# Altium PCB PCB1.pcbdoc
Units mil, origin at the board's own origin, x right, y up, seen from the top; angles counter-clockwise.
Board outline 7296.38 x 4966.72 mil, 2 copper layers (Top Layer, Bottom Layer), stack 62.206 mil thick; 66 components, 34 nets, 136 pads, 49 vias.
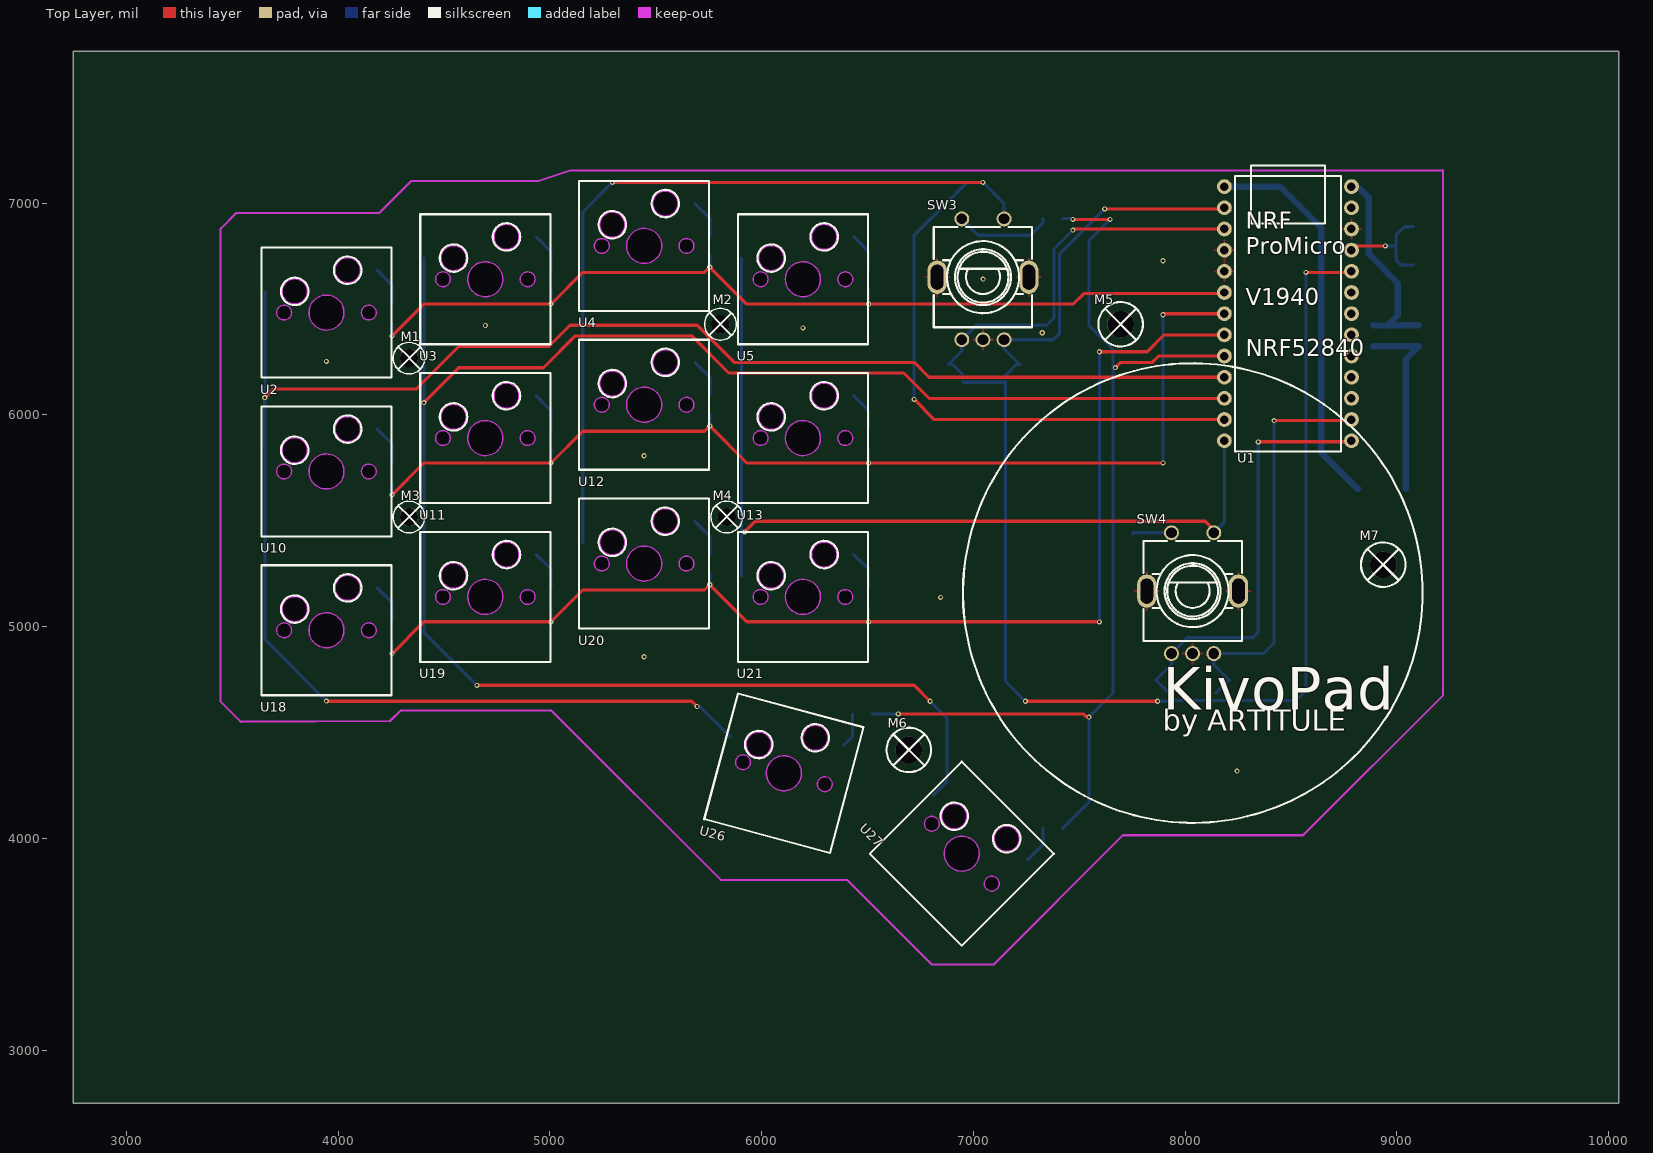
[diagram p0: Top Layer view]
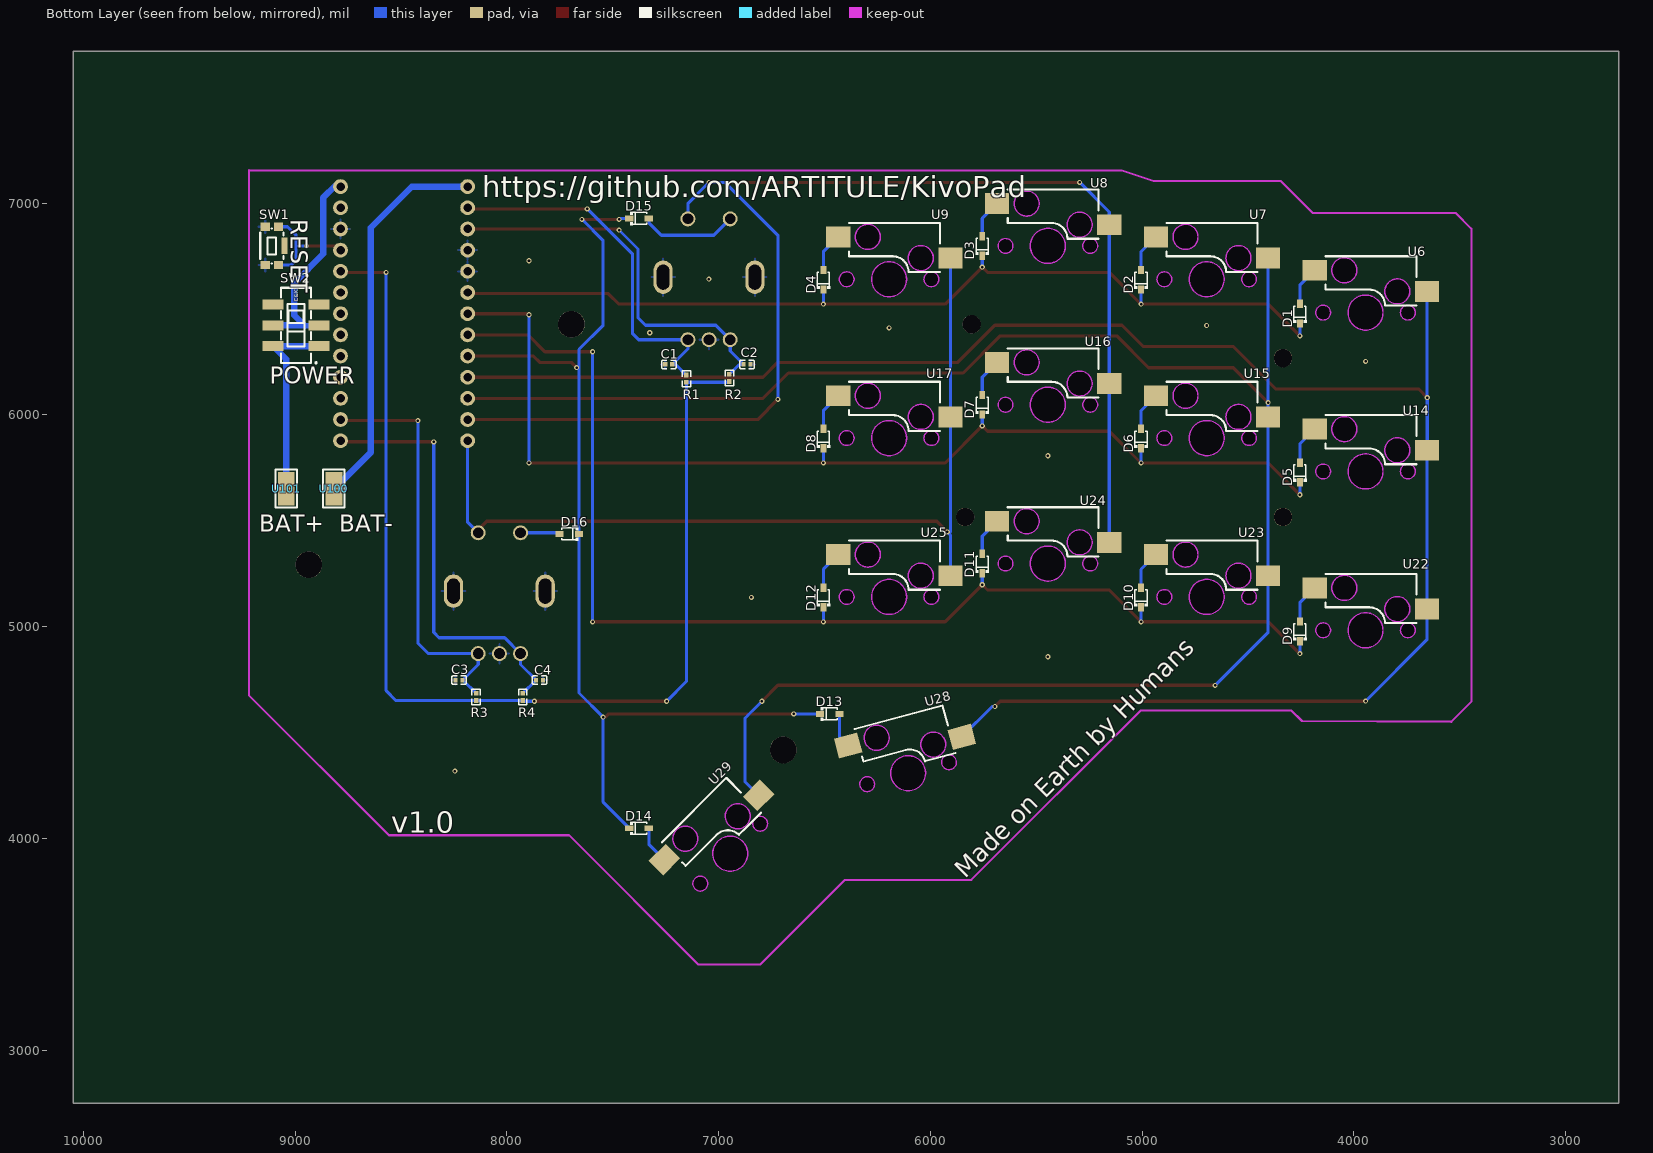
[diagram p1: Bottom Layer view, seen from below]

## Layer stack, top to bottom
Top Solder Mask Layer: solder mask 0.394, Dk 3.3
Top Layer: signal copper 1.379
Dielectric1: surface 59.449, FR4, Dk 4.5
Bottom Layer: signal copper 1.378
Bottom Solder Mask Layer: solder mask 0.394, Dk 3.3

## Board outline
10046.38,2750 2750,2750 2750,7716.72 10046.38,7716.72

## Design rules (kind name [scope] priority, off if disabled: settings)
BoardOutlineClearance copperThickness1oz [All] p0: genericclearance=10 ignorepadtopadclearanceinfootprint=FALSE except(0: Arc-SplitContinuation Track-SplitContinuation SMDPad-SplitContinuation THPad-SplitContinuation Via-SplitContinuation Fill-SplitContinuation Poly-SplitContinuation Region-SplitContinuation Text-SplitContinuation)
BoardOutlineClearance copperThickness2oz [All] p0: genericclearance=10 ignorepadtopadclearanceinfootprint=FALSE except(0: Arc-SplitContinuation Track-SplitContinuation SMDPad-SplitContinuation THPad-SplitContinuation Via-SplitContinuation Fill-SplitContinuation Poly-SplitContinuation Region-SplitContinuation Text-SplitContinuation)
BoardOutlineClearance otherClearance [All] p0: genericclearance=10 ignorepadtopadclearanceinfootprint=FALSE except(0: Arc-SplitContinuation Track-SplitContinuation SMDPad-SplitContinuation THPad-SplitContinuation Via-SplitContinuation Fill-SplitContinuation Poly-SplitContinuation Region-SplitContinuation Text-SplitContinuation)
Clearance copperThickness1oz [All] p1: gap=7 ignorepadtopadclearanceinfootprint=FALSE
Clearance copperThickness2oz [All] p1: gap=7 ignorepadtopadclearanceinfootprint=FALSE
Clearance otherClearance [All] p1: gap=7 ignorepadtopadclearanceinfootprint=FALSE
DiffPairsRouting differentialPair [All] p1: maxuncoupledlength=10 minlimit=6 maxlimit=Infinity mostfreqgap=6 toplayer_minwidth=5 toplayer_prefwidth=10 toplayer_maxwidth=100 bottomlayer_minwidth=5 bottomlayer_prefwidth=10 bottomlayer_maxwidth=100
PasteMaskExpansion pasteMaskExpansion [All] p1: expansion=0
PlaneConnect innerPlane [All] p1: planeconnectstyle=Relief reliefexpansion=20 reliefentries=4 reliefconductorwidth=10 reliefairgap=10
PolygonConnect copperRegion [All] p1: connectstyle=Relief reliefentries=4 reliefconductorwidth=10 polygonreliefangle="90 Angle" airgapwidth=10
RoutingVias viaSize [All] p1: viastyle="Through Hole" holewidth=12.0078 minholewidth=11.811 maxholewidth=248.0314 width=12.0078 minwidth=11.811 maxwidth=248.0314
SolderMaskExpansion solderMaskExpansion [IsVia] p1: useseparateexpansions=TRUE expansion=-1000 expansionbottom=-1000
SolderMaskExpansion solderMaskExpansion [All] p2: useseparateexpansions=TRUE expansion=2 expansionbottom=2
Width copperThickness1oz [All] p1: maxlimit=100 minlimit=5 preferedwidth=10
Width copperThickness2oz [All] p1: maxlimit=100 minlimit=8 preferedwidth=10

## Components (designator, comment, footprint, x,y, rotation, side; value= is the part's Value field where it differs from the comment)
C1 "100nF" C0402 7234.99,6238.32 r180 bottom
C2 "100nF" C0402 6864.99,6238.32 r0 bottom
C3 "100nF" C0402 8224.99,4748.32 r180 bottom
C4 "100nF" C0402 7844.99,4748.32 r0 bottom
D1 "1N4148WS" SOD-323_L1.8-W1.3-LS2.5-RD 4254.99,6478.32 r90 bottom
D2 "1N4148WS" SOD-323_L1.8-W1.3-LS2.5-RD 5004.99,6638.32 r90 bottom
D3 "1N4148WS" SOD-323_L1.8-W1.3-LS2.5-RD 5754.99,6798.32 r90 bottom
D4 "1N4148WS" SOD-323_L1.8-W1.3-LS2.5-RD 6504.99,6638.32 r90 bottom
D5 "1N4148WS" SOD-323_L1.8-W1.3-LS2.5-RD 4254.99,5728.32 r90 bottom
D6 "1N4148WS" SOD-323_L1.8-W1.3-LS2.5-RD 5004.99,5888.32 r90 bottom
D7 "1N4148WS" SOD-323_L1.8-W1.3-LS2.5-RD 5754.99,6048.32 r90 bottom
D8 "1N4148WS" SOD-323_L1.8-W1.3-LS2.5-RD 6504.99,5888.32 r90 bottom
D9 "1N4148WS" SOD-323_L1.8-W1.3-LS2.5-RD 4254.99,4978.32 r90 bottom
D10 "1N4148WS" SOD-323_L1.8-W1.3-LS2.5-RD 5004.99,5138.32 r90 bottom
D11 "1N4148WS" SOD-323_L1.8-W1.3-LS2.5-RD 5754.99,5298.32 r90 bottom
D12 "1N4148WS" SOD-323_L1.8-W1.3-LS2.5-RD 6504.99,5138.32 r90 bottom
D13 "1N4148WS" SOD-323_L1.8-W1.3-LS2.5-RD 6474.99,4588.32 r180 bottom
D14 "1N4148WS" SOD-323_L1.8-W1.3-LS2.5-RD 7374.99,4048.32 r180 bottom
D15 "1N4148WS" SOD-323_L1.8-W1.3-LS2.5-RD 7374.99,6928.32 r180 bottom
D16 "1N4148WS" SOD-323_L1.8-W1.3-LS2.5-RD 7704.99,5438.32 r0 bottom
M1 "" Screw-Hole-M2 4334.99,6268.32 r0 top
M2 "" Screw-Hole-M2 5804.99,6428.32 r0 top
M3 "" Screw-Hole-M2 4334.99,5518.32 r0 top
M4 "" Screw-Hole-M2 5834.99,5518.32 r0 top
M5 "" Screw-Hole-M3 7694.99,6428.32 r0 top
M6 "" Screw-Hole-M3 6694.99,4418.32 r0 top
M7 "" Screw-Hole-M3 8934.9,5293.05 r0 top
R1 "5.1kΩ" R0402 7152.03,6171.28 r90 bottom
R2 "5.1kΩ" R0402 6948.42,6174.63 r90 bottom
R3 "5.1kΩ" R0402 8144.99,4668.32 r90 bottom
R4 "5.1kΩ" R0402 7924.99,4668.32 r90 bottom
SW1 "KMR221GLFS" KEY-SMD_KMR2XXGXXX 9094.99,6798.32 r270 bottom
SW2 "JS202011SCQN" SW-SMD_JS202011SCQN 8994.99,6423.32 r90 bottom
SW3 "EC11E15244B2" SW-TH_EC11XXXXXXXX 7045.03,6640.79 r0 top
SW4 "EC11E15244B2" SW-TH_EC11XXXXXXXX 8034.99,5158.32 r0 top
U1 "NRF_ProMicro" NRF_Pro_Micro 8484.99,6478.32 r0 top
U2 "CPG151101D13" KEY-TH_CPG151101D21X#1 3944.99,6483.36 r0 top
U3 "CPG151101D13" KEY-TH_CPG151101D21X#1 4694.99,6640.84 r0 top
U4 "CPG151101D13" KEY-TH_CPG151101D21X#1 5444.99,6798.32 r0 top
U5 "CPG151101D13" KEY-TH_CPG151101D21X#1 6194.99,6640.84 r0 top
U6 "CPG151101S11-2" TH_L10.9-W5.9-CPG151101S11-2#1 3944.99,6483.36 r0 bottom
U7 "CPG151101S11-2" TH_L10.9-W5.9-CPG151101S11-2#1 4694.99,6640.84 r0 bottom
U8 "CPG151101S11-2" TH_L10.9-W5.9-CPG151101S11-2#1 5444.99,6798.32 r0 bottom
U9 "CPG151101S11-2" TH_L10.9-W5.9-CPG151101S11-2#1 6194.99,6640.84 r0 bottom
U10 "CPG151101D13" KEY-TH_CPG151101D21X#1 3944.99,5733.36 r0 top
U11 "CPG151101D13" KEY-TH_CPG151101D21X#1 4694.99,5890.84 r0 top
U12 "CPG151101D13" KEY-TH_CPG151101D21X#1 5444.99,6048.32 r0 top
U13 "CPG151101D13" KEY-TH_CPG151101D21X#1 6194.99,5890.84 r0 top
U14 "CPG151101S11-2" TH_L10.9-W5.9-CPG151101S11-2#1 3944.99,5733.36 r0 bottom
U15 "CPG151101S11-2" TH_L10.9-W5.9-CPG151101S11-2#1 4694.99,5890.84 r0 bottom
U16 "CPG151101S11-2" TH_L10.9-W5.9-CPG151101S11-2#1 5444.99,6048.32 r0 bottom
U17 "CPG151101S11-2" TH_L10.9-W5.9-CPG151101S11-2#1 6194.99,5890.84 r0 bottom
U18 "CPG151101D13" KEY-TH_CPG151101D21X#1 3944.99,4983.36 r0 top
U19 "CPG151101D13" KEY-TH_CPG151101D21X#1 4694.99,5140.84 r0 top
U20 "CPG151101D13" KEY-TH_CPG151101D21X#1 5444.99,5298.32 r0 top
U21 "CPG151101D13" KEY-TH_CPG151101D21X#1 6194.99,5140.84 r0 top
U22 "CPG151101S11-2" TH_L10.9-W5.9-CPG151101S11-2#1 3944.99,4983.36 r0 bottom
U23 "CPG151101S11-2" TH_L10.9-W5.9-CPG151101S11-2#1 4694.99,5140.84 r0 bottom
U24 "CPG151101S11-2" TH_L10.9-W5.9-CPG151101S11-2#1 5444.99,5298.32 r0 bottom
U25 "CPG151101S11-2" TH_L10.9-W5.9-CPG151101S11-2#1 6194.99,5140.84 r0 bottom
U26 "CPG151101D13" KEY-TH_CPG151101D21X#2 6104.99,4308.32 r345 top
U27 "CPG151101D13" KEY-TH_CPG151101D21X#3 6944.99,3928.32 r315 top
U28 "CPG151101S11-2" TH_L10.9-W5.9-CPG151101S11-2#1 6104.99,4308.32 r345 bottom
U29 "CPG151101S11-2" TH_L10.9-W5.9-CPG151101S11-2#2 6944.99,3928.32 r315 bottom
U100 "" Pad2mmx4mm 8894.99,5573.32 r180 bottom
U101 "" Pad2mmx4mm 9119.99,5573.32 r180 bottom

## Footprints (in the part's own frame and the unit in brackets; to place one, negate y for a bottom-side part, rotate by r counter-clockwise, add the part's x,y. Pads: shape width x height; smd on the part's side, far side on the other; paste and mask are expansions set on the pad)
C0402 [mm]
  rect 0.5x0.54 smd paste+0 mask+0.051: 1(-0.42,0) 2(0.42,0)
  silkscreen extent -0.87,-0.5 0.87,0.5
KEY-SMD_KMR2XXGXXX [mm]
  rect 1x1.1 smd: 1(-2.3,0.438) 2(2.3,0.438) 3(-2.3,-1.162) 4(2.3,-1.162)
  rect 2x0.7 smd: 5(0,1.162)
  silkscreen extent -2.1,-1.76 2.1,1.04
KEY-TH_CPG151101D21X#1 [mil]
  Board Outline Layer circle w0.1: c0,0 r82.68
  Board Outline Layer circle w0.1: c-200,0 r35
  Board Outline Layer circle w0.1: c200,0 r35
  Board Outline Layer region: 82.68,0 74.49,-35.87 51.55,-64.64 18.4,-80.6 -18.4,-80.6 -51.55,-64.64 -74.49,-35.87 -82.68,0 -82.68,0 -74.49,35.87 -51.55,64.64 -18.4,80.6 18.4,80.6 51.55,64.64 74.49,35.87 82.68,0
  Board Outline Layer region: 82.68,0 82.28,-8.1 81.09,-16.13 79.12,-24 76.38,-31.64 72.91,-38.97 68.74,-45.93 63.91,-52.45 58.46,-58.46 52.45,-63.91 45.93,-68.74 38.97,-72.91 31.64,-76.38 24,-79.12 16.13,-81.09 8.1,-82.28 0,-82.68 -8.1,-82.28 -16.13,-81.09 -24,-79.12 -31.64,-76.38 -38.97,-72.91 -45.93,-68.74 -52.45,-63.91 -58.46,-58.46 -63.91,-52.45 -68.74,-45.93 -72.91,-38.97 -76.38,-31.64 -79.12,-24 -81.09,-16.13 -82.28,-8.1 -82.68,0 -82.28,8.1 -81.09,16.13 -79.12,24 -76.38,31.64 -72.91,38.97 -68.74,45.93 -63.91,52.45 -58.46,58.46 -52.45,63.91 -45.93,68.74 -38.97,72.91 -31.64,76.38 -24,79.12 -16.13,81.09 -8.1,82.28 0,82.68 8.1,82.28 16.13,81.09 24,79.12 31.64,76.38 38.97,72.91 45.93,68.74 52.45,63.91 58.46,58.46 63.91,52.45 68.74,45.93 72.91,38.97 76.38,31.64 79.12,24 81.09,16.13 82.28,8.1
  Board Outline Layer region: -165,0 -168.47,-15.19 -178.18,-27.36 -192.21,-34.12 -207.79,-34.12 -221.82,-27.36 -231.53,-15.19 -235,0 -235,0 -231.53,15.19 -221.82,27.36 -207.79,34.12 -192.21,34.12 -178.18,27.36 -168.47,15.19 -165,0
  Board Outline Layer region: -165,0 -165.39,-5.22 -166.55,-10.32 -168.47,-15.19 -171.08,-19.72 -174.34,-23.81 -178.18,-27.36 -182.5,-30.31 -187.21,-32.58 -192.21,-34.12 -197.38,-34.9 -202.62,-34.9 -207.79,-34.12 -212.79,-32.58 -217.5,-30.31 -221.82,-27.36 -225.66,-23.81 -228.92,-19.72 -231.53,-15.19 -233.45,-10.32 -234.61,-5.22 -235,0 -234.61,5.22 -233.45,10.32 -231.53,15.19 -228.92,19.72 -225.66,23.81 -221.82,27.36 -217.5,30.31 -212.79,32.58 -207.79,34.12 -202.62,34.9 -197.38,34.9 -192.21,34.12 -187.21,32.58 -182.5,30.31 -178.18,27.36 -174.34,23.81 -171.08,19.72 -168.47,15.19 -166.55,10.32 -165.39,5.22
  Board Outline Layer region: 235,0 231.53,-15.19 221.82,-27.36 207.79,-34.12 192.21,-34.12 178.18,-27.36 168.47,-15.19 165,0 165,0 168.47,15.19 178.18,27.36 192.21,34.12 207.79,34.12 221.82,27.36 231.53,15.19 235,0
  Board Outline Layer region: 235,0 234.61,-5.22 233.44,-10.32 231.53,-15.19 228.92,-19.72 225.66,-23.81 221.82,-27.36 217.5,-30.31 212.79,-32.58 207.79,-34.12 202.62,-34.9 197.38,-34.9 192.21,-34.12 187.21,-32.58 182.5,-30.31 178.18,-27.36 174.34,-23.81 171.08,-19.72 168.47,-15.19 166.56,-10.32 165.39,-5.22 165,0 165.39,5.22 166.56,10.32 168.47,15.19 171.08,19.72 174.34,23.81 178.18,27.36 182.5,30.31 187.21,32.58 192.21,34.12 197.38,34.9 202.62,34.9 207.79,34.12 212.79,32.58 217.5,30.31 221.82,27.36 225.66,23.81 228.92,19.72 231.53,15.19 233.44,10.32 234.61,5.22
  Multi-Layer board cut-out: 82.68,0 74.49,-35.87 51.55,-64.64 18.4,-80.6 -18.4,-80.6 -51.55,-64.64 -74.49,-35.87 -82.68,0 -82.68,0 -74.49,35.87 -51.55,64.64 -18.4,80.6 18.4,80.6 51.55,64.64 74.49,35.87 82.68,0
  Multi-Layer board cut-out: -165,0 -168.47,-15.19 -178.18,-27.36 -192.21,-34.12 -207.79,-34.12 -221.82,-27.36 -231.53,-15.19 -235,0 -235,0 -231.53,15.19 -221.82,27.36 -207.79,34.12 -192.21,34.12 -178.18,27.36 -168.47,15.19 -165,0
  Multi-Layer board cut-out: 235,0 231.53,-15.19 221.82,-27.36 207.79,-34.12 192.21,-34.12 178.18,-27.36 168.47,-15.19 165,0 165,0 168.47,15.19 178.18,27.36 192.21,34.12 207.79,34.12 221.82,27.36 231.53,15.19 235,0
  silkscreen extent -307,-307 307,307
KEY-TH_CPG151101D21X#2 [mil]
  Board Outline Layer circle w0.1: c0,0 r82.68
  Board Outline Layer circle w0.1: c-200,0 r35
  Board Outline Layer circle w0.1: c200,0 r35
  Board Outline Layer region: 79.86,21.4 81.24,-15.37 66.52,-49.1 38.63,-73.1 3.09,-82.62 -33.06,-75.78 -62.67,-53.93 -79.86,-21.4 -79.86,-21.4 -81.24,15.37 -66.52,49.1 -38.63,73.1 -3.09,82.62 33.06,75.78 62.67,53.93 79.86,21.4
  Board Outline Layer region: 79.86,21.4 81.57,13.47 82.5,5.41 82.63,-2.71 81.97,-10.79 80.52,-18.77 78.29,-26.58 75.31,-34.12 71.6,-41.34 67.2,-48.16 62.16,-54.51 56.52,-60.34 50.33,-65.59 43.66,-70.21 36.57,-74.15 29.12,-77.38 21.4,-79.86 13.47,-81.57 5.41,-82.5 -2.71,-82.63 -10.79,-81.97 -18.77,-80.52 -26.58,-78.29 -34.12,-75.31 -41.34,-71.6 -48.16,-67.2 -54.51,-62.16 -60.34,-56.52 -65.59,-50.33 -70.21,-43.66 -74.15,-36.57 -77.38,-29.12 -79.86,-21.4 -81.57,-13.47 -82.5,-5.41 -82.63,2.71 -81.97,10.79 -80.52,18.77 -78.29,26.58 -75.31,34.12 -71.6,41.34 -67.2,48.16 -62.16,54.51 -56.52,60.34 -50.33,65.59 -43.66,70.21 -36.57,74.15 -29.12,77.38 -21.4,79.86 -13.47,81.57 -5.41,82.5 2.71,82.63 10.79,81.97 18.77,80.52 26.58,78.29 34.12,75.31 41.34,71.6 48.16,67.2 54.51,62.16 60.34,56.52 65.59,50.33 70.21,43.66 74.15,36.57 77.38,29.12
  Board Outline Layer region: -166.19,9.06 -165.61,-6.51 -171.84,-20.78 -183.65,-30.94 -198.69,-34.98 -214,-32.08 -226.53,-22.83 -233.81,-9.06 -233.81,-9.06 -234.39,6.51 -228.16,20.78 -216.35,30.94 -201.31,34.98 -186,32.08 -173.47,22.83 -166.19,9.06
  Board Outline Layer region: -166.19,9.06 -165.22,3.92 -165.02,-1.31 -165.61,-6.51 -166.96,-11.56 -169.06,-16.35 -171.84,-20.78 -175.25,-24.75 -179.22,-28.16 -183.65,-30.94 -188.44,-33.04 -193.49,-34.39 -198.69,-34.98 -203.92,-34.78 -209.06,-33.81 -214,-32.08 -218.62,-29.64 -222.83,-26.53 -226.53,-22.83 -229.64,-18.62 -232.08,-14 -233.81,-9.06 -234.78,-3.92 -234.98,1.31 -234.39,6.51 -233.04,11.56 -230.94,16.35 -228.16,20.78 -224.75,24.75 -220.78,28.16 -216.35,30.94 -211.56,33.04 -206.51,34.39 -201.31,34.98 -196.08,34.78 -190.94,33.81 -186,32.08 -181.38,29.64 -177.17,26.53 -173.47,22.83 -170.36,18.62 -167.92,14
  Board Outline Layer region: 233.81,9.06 234.39,-6.51 228.16,-20.78 216.35,-30.94 201.31,-34.98 186,-32.08 173.47,-22.83 166.19,-9.06 166.19,-9.06 165.61,6.51 171.84,20.78 183.65,30.94 198.69,34.98 214,32.08 226.53,22.83 233.81,9.06
  Board Outline Layer region: 233.81,9.06 234.78,3.92 234.98,-1.31 234.39,-6.51 233.04,-11.56 230.94,-16.35 228.16,-20.78 224.75,-24.75 220.78,-28.16 216.35,-30.94 211.56,-33.04 206.51,-34.39 201.31,-34.98 196.08,-34.78 190.94,-33.81 186,-32.08 181.38,-29.64 177.17,-26.53 173.47,-22.83 170.36,-18.62 167.92,-14 166.19,-9.06 165.22,-3.92 165.02,1.31 165.61,6.51 166.96,11.56 169.06,16.35 171.84,20.78 175.25,24.75 179.22,28.16 183.65,30.94 188.44,33.04 193.49,34.39 198.69,34.98 203.92,34.78 209.06,33.81 214,32.08 218.62,29.64 222.83,26.53 226.53,22.83 229.64,18.62 232.08,14
  Multi-Layer board cut-out: 79.86,21.4 81.24,-15.37 66.52,-49.1 38.63,-73.1 3.09,-82.62 -33.06,-75.78 -62.67,-53.93 -79.86,-21.4 -79.86,-21.4 -81.24,15.37 -66.52,49.1 -38.63,73.1 -3.09,82.62 33.06,75.78 62.67,53.93 79.86,21.4
  Multi-Layer board cut-out: -166.19,9.06 -165.61,-6.51 -171.84,-20.78 -183.65,-30.94 -198.69,-34.98 -214,-32.08 -226.53,-22.83 -233.81,-9.06 -233.81,-9.06 -234.39,6.51 -228.16,20.78 -216.35,30.94 -201.31,34.98 -186,32.08 -173.47,22.83 -166.19,9.06
  Multi-Layer board cut-out: 233.81,9.06 234.39,-6.51 228.16,-20.78 216.35,-30.94 201.31,-34.98 186,-32.08 173.47,-22.83 166.19,-9.06 166.19,-9.06 165.61,6.51 171.84,20.78 183.65,30.94 198.69,34.98 214,32.08 226.53,22.83 233.81,9.06
  silkscreen extent -307,-307 307,307
KEY-TH_CPG151101D21X#3 [mil]
  Board Outline Layer circle w0.1: c0,0 r82.68
  Board Outline Layer circle w0.1: c-200,0 r35
  Board Outline Layer circle w0.1: c200,0 r35
  Board Outline Layer region: 58.46,58.46 78.04,27.31 82.16,-9.26 70,-43.99 43.99,-70 9.26,-82.16 -27.31,-78.04 -58.46,-58.46 -58.46,-58.46 -78.04,-27.31 -82.16,9.26 -70,43.99 -43.99,70 -9.26,82.16 27.31,78.04 58.46,58.46
  Board Outline Layer region: 58.46,58.46 63.91,52.45 68.74,45.93 72.91,38.97 76.38,31.64 79.12,24 81.09,16.13 82.28,8.1 82.68,0 82.28,-8.1 81.09,-16.13 79.12,-24 76.38,-31.64 72.91,-38.97 68.74,-45.93 63.91,-52.45 58.46,-58.46 52.45,-63.91 45.93,-68.74 38.97,-72.91 31.64,-76.38 24,-79.12 16.13,-81.09 8.1,-82.28 0,-82.68 -8.1,-82.28 -16.13,-81.09 -24,-79.12 -31.64,-76.38 -38.97,-72.91 -45.93,-68.74 -52.45,-63.91 -58.46,-58.46 -63.91,-52.45 -68.74,-45.93 -72.91,-38.97 -76.38,-31.64 -79.12,-24 -81.09,-16.13 -82.28,-8.1 -82.68,0 -82.28,8.1 -81.09,16.13 -79.12,24 -76.38,31.64 -72.91,38.97 -68.74,45.93 -63.91,52.45 -58.46,58.46 -52.45,63.91 -45.93,68.74 -38.97,72.91 -31.64,76.38 -24,79.12 -16.13,81.09 -8.1,82.28 0,82.68 8.1,82.28 16.13,81.09 24,79.12 31.64,76.38 38.97,72.91 45.93,68.74 52.45,63.91
  Board Outline Layer region: -175.25,24.75 -166.96,11.56 -165.22,-3.92 -170.36,-18.62 -181.38,-29.64 -196.08,-34.78 -211.56,-33.04 -224.75,-24.75 -224.75,-24.75 -233.04,-11.56 -234.78,3.92 -229.64,18.62 -218.62,29.64 -203.92,34.78 -188.44,33.04 -175.25,24.75
  Board Outline Layer region: -175.25,24.75 -171.84,20.78 -169.06,16.35 -166.96,11.56 -165.61,6.51 -165.02,1.31 -165.22,-3.92 -166.19,-9.06 -167.92,-14 -170.36,-18.62 -173.47,-22.83 -177.17,-26.53 -181.38,-29.64 -186,-32.08 -190.94,-33.81 -196.08,-34.78 -201.31,-34.98 -206.51,-34.39 -211.56,-33.04 -216.35,-30.94 -220.78,-28.16 -224.75,-24.75 -228.16,-20.78 -230.94,-16.35 -233.04,-11.56 -234.39,-6.51 -234.98,-1.31 -234.78,3.92 -233.81,9.06 -232.08,14 -229.64,18.62 -226.53,22.83 -222.83,26.53 -218.62,29.64 -214,32.08 -209.06,33.81 -203.92,34.78 -198.69,34.98 -193.49,34.39 -188.44,33.04 -183.65,30.94 -179.22,28.16
  Board Outline Layer region: 224.75,24.75 233.04,11.56 234.78,-3.92 229.64,-18.62 218.62,-29.64 203.92,-34.78 188.44,-33.04 175.25,-24.75 175.25,-24.75 166.96,-11.56 165.22,3.92 170.36,18.62 181.38,29.64 196.08,34.78 211.56,33.04 224.75,24.75
  Board Outline Layer region: 224.75,24.75 228.16,20.78 230.94,16.35 233.04,11.56 234.39,6.51 234.98,1.31 234.78,-3.92 233.81,-9.06 232.08,-14 229.64,-18.62 226.53,-22.83 222.83,-26.53 218.62,-29.64 214,-32.08 209.06,-33.81 203.92,-34.78 198.69,-34.98 193.49,-34.39 188.44,-33.04 183.65,-30.94 179.22,-28.16 175.25,-24.75 171.84,-20.78 169.06,-16.35 166.96,-11.56 165.61,-6.51 165.02,-1.31 165.22,3.92 166.19,9.06 167.92,14 170.36,18.62 173.47,22.83 177.17,26.53 181.38,29.64 186,32.08 190.94,33.81 196.08,34.78 201.31,34.98 206.51,34.39 211.56,33.04 216.35,30.94 220.78,28.16
  Multi-Layer board cut-out: 58.46,58.46 78.04,27.31 82.16,-9.26 70,-43.99 43.99,-70 9.26,-82.16 -27.31,-78.04 -58.46,-58.46 -58.46,-58.46 -78.04,-27.31 -82.16,9.26 -70,43.99 -43.99,70 -9.26,82.16 27.31,78.04 58.46,58.46
  Multi-Layer board cut-out: -175.25,24.75 -166.96,11.56 -165.22,-3.92 -170.36,-18.62 -181.38,-29.64 -196.08,-34.78 -211.56,-33.04 -224.75,-24.75 -224.75,-24.75 -233.04,-11.56 -234.78,3.92 -229.64,18.62 -218.62,29.64 -203.92,34.78 -188.44,33.04 -175.25,24.75
  Multi-Layer board cut-out: 224.75,24.75 233.04,11.56 234.78,-3.92 229.64,-18.62 218.62,-29.64 203.92,-34.78 188.44,-33.04 175.25,-24.75 175.25,-24.75 166.96,-11.56 165.22,3.92 170.36,18.62 181.38,29.64 196.08,34.78 211.56,33.04 224.75,24.75
  silkscreen extent -307,-307 307,307
NRF_Pro_Micro [mil]
  round 70 hole 40: 1(-300,600) 2(-300,500) 3(-300,400) 4(-300,300) 5(-300,200) 6(-300,100) 7(-300,0) 8(-300,-100) 9(-300,-200) 10(-300,-300) 11(-300,-400) 12(-300,-500) 13(-300,-600) 14(300,-600) 15(300,-500) 16(300,-400) 17(300,-300) 18(300,-200) 19(300,-100) 20(300,0) 21(300,100) 22(300,200) 23(300,300) 24(300,400) 25(300,500) 26(300,600)
  silkscreen extent -250,-650 250,700
Pad2mmx4mm [mm]
  rect 2x4 smd: 1(2,2)
  silkscreen extent 0.71,-0.28 3.28,4.29
R0402 [mm]
  rect 0.566x0.54 smd paste-100 mask+0.051: 1(-0.433,0) 2(0.433,0)
  silkscreen extent -0.94,-0.5 0.94,0.5
Screw-Hole-M2 [mm]
  round 2.2 hole 2.2: 1(0,0)
  silkscreen extent -1.9,-1.9 1.9,1.9
Screw-Hole-M3 [mil]
  round 126 hole 126 paste+0 mask+4: 1(0,0)
  silkscreen extent -105,-105 105,105
SOD-323_L1.8-W1.3-LS2.5-RD [mm]
  rect 1x0.7 smd: 1(-1.172,0) 2(1.172,0)
  silkscreen extent -1.08,-0.8 0.9,0.8
SW-SMD_JS202011SCQN [mm]
  rect 1.2x2.5 smd paste+0 mask+0.051: 1(-2.5,-2.75) 2(0,-2.75) 3(2.5,-2.75) 4(-2.5,2.75) 5(0,2.75) 6(2.5,2.75)
  silkscreen extent -4.6,-2.5 4.5,1.8
SW-TH_EC11XXXXXXXX [mm]
  oval 2.3x4 hole 1.5 slot 3 at 90 deg: 6(5.5,0.25) 7(-5.5,0.25)
  round 1.8 hole 1.3: A(-2.54,-7.25) B(2.54,-7.25) C(0,-7.25) D(-2.54,7.25) E(2.54,7.25)
  silkscreen extent -5.9,-5.75 5.9,6.25
TH_L10.9-W5.9-CPG151101S11-2#1 [mm]
  rect 2.9x2.5 smd paste-100 mask+0.05: 1(-7.36,-2.54) 2(6.09,-5.08)
  Board Outline Layer circle w0.003: c2.54,-5.08 r1.5
  Board Outline Layer circle w0.003: c-3.81,-2.54 r1.5
  Board Outline Layer region: 4.04,-5.08 3.891,-4.429 3.475,-3.907 2.874,-3.618 2.206,-3.618 1.605,-3.907 1.189,-4.429 1.04,-5.08 1.04,-5.08 1.189,-5.731 1.605,-6.253 2.206,-6.542 2.874,-6.542 3.475,-6.253 3.891,-5.731 4.04,-5.08
  Board Outline Layer region: 4.04,-5.08 4.03,-4.906 4,-4.734 3.95,-4.567 3.88,-4.407 3.793,-4.256 3.689,-4.116 3.569,-3.989 3.436,-3.877 3.29,-3.781 3.134,-3.703 2.97,-3.643 2.8,-3.603 2.627,-3.583 2.453,-3.583 2.28,-3.603 2.11,-3.643 1.946,-3.703 1.79,-3.781 1.644,-3.877 1.511,-3.989 1.391,-4.116 1.287,-4.256 1.2,-4.407 1.13,-4.567 1.08,-4.734 1.05,-4.906 1.04,-5.08 1.05,-5.254 1.08,-5.426 1.13,-5.593 1.2,-5.753 1.287,-5.904 1.391,-6.044 1.511,-6.171 1.644,-6.283 1.79,-6.379 1.946,-6.457 2.11,-6.517 2.28,-6.557 2.453,-6.577 2.627,-6.577 2.8,-6.557 2.97,-6.517 3.134,-6.457 3.29,-6.379 3.436,-6.283 3.569,-6.171 3.689,-6.044 3.793,-5.904 3.88,-5.753 3.95,-5.593 4,-5.426 4.03,-5.254
  Board Outline Layer region: -2.31,-2.54 -2.459,-1.889 -2.875,-1.367 -3.476,-1.078 -4.144,-1.078 -4.745,-1.367 -5.161,-1.889 -5.31,-2.54 -5.31,-2.54 -5.161,-3.191 -4.745,-3.713 -4.144,-4.002 -3.476,-4.002 -2.875,-3.713 -2.459,-3.191 -2.31,-2.54
  Board Outline Layer region: -2.31,-2.54 -2.32,-2.366 -2.35,-2.194 -2.4,-2.027 -2.47,-1.867 -2.557,-1.716 -2.661,-1.576 -2.781,-1.449 -2.914,-1.337 -3.06,-1.241 -3.216,-1.163 -3.38,-1.103 -3.55,-1.063 -3.723,-1.043 -3.897,-1.043 -4.07,-1.063 -4.24,-1.103 -4.404,-1.163 -4.56,-1.241 -4.706,-1.337 -4.839,-1.449 -4.959,-1.576 -5.063,-1.716 -5.15,-1.867 -5.22,-2.027 -5.27,-2.194 -5.3,-2.366 -5.31,-2.54 -5.3,-2.714 -5.27,-2.886 -5.22,-3.053 -5.15,-3.213 -5.063,-3.364 -4.959,-3.504 -4.839,-3.631 -4.706,-3.743 -4.56,-3.839 -4.404,-3.917 -4.24,-3.977 -4.07,-4.017 -3.897,-4.037 -3.723,-4.037 -3.55,-4.017 -3.38,-3.977 -3.216,-3.917 -3.06,-3.839 -2.914,-3.743 -2.781,-3.631 -2.661,-3.504 -2.557,-3.364 -2.47,-3.213 -2.4,-3.053 -2.35,-2.886 -2.32,-2.714
  Multi-Layer board cut-out: 4.04,-5.08 3.891,-4.429 3.475,-3.907 2.874,-3.618 2.206,-3.618 1.605,-3.907 1.189,-4.429 1.04,-5.08 1.04,-5.08 1.189,-5.731 1.605,-6.253 2.206,-6.542 2.874,-6.542 3.475,-6.253 3.891,-5.731 4.04,-5.08
  Multi-Layer board cut-out: -2.31,-2.54 -2.459,-1.889 -2.875,-1.367 -3.476,-1.078 -4.144,-1.078 -4.745,-1.367 -5.161,-1.889 -5.31,-2.54 -5.31,-2.54 -5.161,-3.191 -4.745,-3.713 -4.144,-4.002 -3.476,-4.002 -2.875,-3.713 -2.459,-3.191 -2.31,-2.54
  silkscreen extent -6.1,-6.76 4.82,-0.86
TH_L10.9-W5.9-CPG151101S11-2#2 [mm]
  rect 2.9x2.5 smd paste-100 mask+0.05: 1(-7.36,-2.54) 2(6.09,-5.08)
  Board Outline Layer circle w0.003: c2.54,-5.08 r1.5
  Board Outline Layer circle w0.003: c-3.81,-2.54 r1.5
  Board Outline Layer region: 3.601,-6.141 3.956,-5.575 4.031,-4.912 3.81,-4.282 3.338,-3.81 2.708,-3.589 2.045,-3.664 1.479,-4.019 1.479,-4.019 1.124,-4.585 1.049,-5.248 1.27,-5.878 1.742,-6.35 2.372,-6.571 3.035,-6.496 3.601,-6.141
  Board Outline Layer region: 3.601,-6.141 3.717,-6.01 3.817,-5.867 3.899,-5.714 3.964,-5.552 4.009,-5.383 4.034,-5.211 4.039,-5.036 4.024,-4.863 3.989,-4.692 3.934,-4.526 3.86,-4.368 3.769,-4.22 3.661,-4.083 3.537,-3.959 3.4,-3.851 3.252,-3.76 3.094,-3.686 2.928,-3.631 2.757,-3.596 2.584,-3.581 2.409,-3.586 2.237,-3.611 2.068,-3.656 1.906,-3.721 1.753,-3.803 1.61,-3.903 1.479,-4.019 1.363,-4.15 1.263,-4.293 1.181,-4.446 1.116,-4.608 1.071,-4.777 1.046,-4.949 1.041,-5.124 1.056,-5.297 1.091,-5.468 1.146,-5.634 1.22,-5.792 1.311,-5.94 1.419,-6.077 1.543,-6.201 1.68,-6.309 1.828,-6.4 1.986,-6.474 2.152,-6.529 2.323,-6.564 2.496,-6.579 2.671,-6.574 2.843,-6.549 3.012,-6.504 3.174,-6.439 3.327,-6.357 3.47,-6.257
  Board Outline Layer region: -2.749,-3.601 -2.394,-3.035 -2.319,-2.372 -2.54,-1.742 -3.012,-1.27 -3.642,-1.049 -4.305,-1.124 -4.871,-1.479 -4.871,-1.479 -5.226,-2.045 -5.301,-2.708 -5.08,-3.338 -4.608,-3.81 -3.978,-4.031 -3.315,-3.956 -2.749,-3.601
  Board Outline Layer region: -2.749,-3.601 -2.633,-3.47 -2.533,-3.327 -2.451,-3.174 -2.386,-3.012 -2.341,-2.843 -2.316,-2.671 -2.311,-2.496 -2.326,-2.323 -2.361,-2.152 -2.416,-1.986 -2.49,-1.828 -2.581,-1.68 -2.689,-1.543 -2.813,-1.419 -2.95,-1.311 -3.098,-1.22 -3.256,-1.146 -3.422,-1.091 -3.593,-1.056 -3.766,-1.041 -3.941,-1.046 -4.113,-1.071 -4.282,-1.116 -4.444,-1.181 -4.597,-1.263 -4.74,-1.363 -4.871,-1.479 -4.987,-1.61 -5.087,-1.753 -5.169,-1.906 -5.234,-2.068 -5.279,-2.237 -5.304,-2.409 -5.309,-2.584 -5.294,-2.757 -5.259,-2.928 -5.204,-3.094 -5.13,-3.252 -5.039,-3.4 -4.931,-3.537 -4.807,-3.661 -4.67,-3.769 -4.522,-3.86 -4.364,-3.934 -4.198,-3.989 -4.027,-4.024 -3.854,-4.039 -3.679,-4.034 -3.507,-4.009 -3.338,-3.964 -3.176,-3.899 -3.023,-3.817 -2.88,-3.717
  Multi-Layer board cut-out: 3.601,-6.141 3.956,-5.575 4.031,-4.912 3.81,-4.282 3.338,-3.81 2.708,-3.589 2.045,-3.664 1.479,-4.019 1.479,-4.019 1.124,-4.585 1.049,-5.248 1.27,-5.878 1.742,-6.35 2.372,-6.571 3.035,-6.496 3.601,-6.141
  Multi-Layer board cut-out: -2.749,-3.601 -2.394,-3.035 -2.319,-2.372 -2.54,-1.742 -3.012,-1.27 -3.642,-1.049 -4.305,-1.124 -4.871,-1.479 -4.871,-1.479 -5.226,-2.045 -5.301,-2.708 -5.08,-3.338 -4.608,-3.81 -3.978,-4.031 -3.315,-3.956 -2.749,-3.601
  silkscreen extent -6.1,-6.76 4.82,-0.86

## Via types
v1: diameter 24.02, hole 12, Top Layer to Bottom Layer, 49 vias

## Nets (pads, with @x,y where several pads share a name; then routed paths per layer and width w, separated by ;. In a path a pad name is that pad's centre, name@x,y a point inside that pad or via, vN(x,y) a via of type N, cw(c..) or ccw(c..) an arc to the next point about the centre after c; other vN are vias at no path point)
$1N13: D13.2 U28.2 | length 165.6
  Bottom Layer w15: U28.2 6428.83,4479.93 D13.2
$1N14: D9.2 U22.2 | length 188
  Bottom Layer w15: U22.2 4254.99,5113.12 D9.2
$1N15: D5.2 U14.2 | length 188
  Bottom Layer w15: U14.2 4254.99,5863.12 D5.2
$1N16: D1.2 U6.2 | length 188
  Bottom Layer w15: U6.2 4254.99,6613.12 D1.2
$1N17: D2.2 U7.2 | length 185.5
  Bottom Layer w15: U7.2 5004.99,6770.6 D2.2
$1N18: D6.2 U15.2 | length 185.5
  Bottom Layer w15: U15.2 5004.99,6020.6 D6.2
$1N19: D10.2 U23.2 | length 185.5
  Bottom Layer w15: U23.2 5004.99,5270.6 D10.2
$1N20: D14.2 U29.2 | length 178.3
  Bottom Layer w15: U29.2 7328.83,3973.09 D14.2
$1N23: D12.2 U25.2 | length 185.5
  Bottom Layer w15: U25.2 6504.99,5270.6 D12.2
$1N24: D11.2 U24.2 | length 182.9
  Bottom Layer w15: U24.2 5754.99,5428.08 D11.2
$1N25: D7.2 U16.2 | length 182.9
  Bottom Layer w15: U16.2 5754.99,6178.08 D7.2
$1N26: D8.2 U17.2 | length 185.5
  Bottom Layer w15: U17.2 6504.99,6020.6 D8.2
$1N27: D3.2 U8.2 | length 182.9
  Bottom Layer w15: U8.2 5754.99,6928.08 D3.2
$1N28: D4.2 U9.2 | length 185.5
  Bottom Layer w15: U9.2 6504.99,6770.6 D4.2
$1N61: SW1.1 SW1.2 U1.23 | length 527.2
  Top Layer w15: U1.23 8804.99,6798.32 v1(8944.99,6798.32)
  Bottom Layer w15: v1(8944.99,6798.32) 8993.23,6798.32 8994.99,6800.07 ; SW1.2 9019.99,6707.77 8994.99,6732.77 8994.99,6800.07 ; SW1.1 9035.54,6888.87 8994.99,6848.32 8994.99,6800.07
+3V3: R1.1 R2.1 R3.1 R4.1 U1.22 | length 5287.2
  Top Layer w15: v1(7244.99,4648.32) v1(7869.99,4648.32) ; v1(8569.99,6673.32) 8779.99,6673.32 U1.22
  Bottom Layer w15: R2.1 6951.77,6154.24 R1.1 7152.03,4741.28 v1(7244.99,4648.32) ; v1(7869.99,4648.32) 7922.03,4648.32 R4.1 R3.1 8522.95,4651.28 8569.99,4698.32 v1(8569.99,6673.32)
BAT+: SW2.2 SW2.5 U1.26 | length 1005.8
  Bottom Layer w30: U1.26@8781.7,7082.73 8810.08,7082.73 8865.87,7026.94 8865.87,6760.71 9003.88,6622.71 9003.88,6471 8956.2,6423.32 ; SW2.2 8888.38,6423.32 8952.98,6420.1 8956.2,6423.32 ; SW2.5 8956.2,6423.32
BAT+_BS: SW2.1 SW2.4 U101.1 | length 915.1
  Bottom Layer w30: SW2.1 SW2.4 9041.25,6262.89 U101.1
BAT-: U1.1 U100.1 | length 1847.6
  Bottom Layer w30: U1.1@8180.64,7077.71 8448.98,7077.71 8642.85,6883.84 8642.85,5822.85 8813.65,5652.06 U100.1
COL0: U1.10 U6.1 U14.1 U22.1 U28.1 | length 8806.2
  Top Layer w15: v1(3653.68,6082.01) 3694.99,6123.32 4369.99,6123.32 4569.99,6323.32 4994.99,6323.32 5094.99,6423.32 5694.99,6423.32 5869.99,6248.32 6719.99,6248.32 6789.99,6178.32 U1.10 ; v1(3944.91,4648.41) 3945.01,4648.32 5669.99,4648.32 v1(5694.99,4623.32)
  Bottom Layer w15: U6.1 3655.23,6083.56 v1(3653.68,6082.01) 3653.68,5834.9 U14.1 U22.1 3655.23,4938.1 v1(3944.91,4648.41) ; v1(5694.99,4623.32) 5707.57,4623.32 U28.1
COL1: U1.11 U7.1 U15.1 U23.1 U29.1 | length 8828.8
  Top Layer w15: v1(4405.1,6058.43) 4569.99,6223.32 4969.99,6223.32 5119.99,6373.32 5669.99,6373.32 5844.99,6198.32 6669.99,6198.32 6789.99,6078.32 U1.11 ; v1(4655.23,4723.32) 6719.99,4723.32 v1(6794.99,4648.32)
  Bottom Layer w15: v1(4405.1,6058.43) v1@4405.23,6058.56 ; U7.1 v1@4405.23,6058.56 ; v1(4655.23,4723.32) 4405.23,4973.32 U23.1 U15.1 v1@4405.23,6058.56 ; v1(6794.99,4648.32) 6875.15,4568.15 6875.15,4268.27 U29.1
COL2: SW3.E U1.12 U8.1 U16.1 U24.1 | length 6429.3
  Top Layer w15: v1(5294.99,7098.32) v1(7044.99,7098.32) ; v1(6719.99,6073.32) 6814.99,5978.32 U1.12
  Bottom Layer w15: U24.1 U16.1 U8.1 5155.23,6958.56 v1(5294.99,7098.32) ; v1(6719.99,6073.32) 6719.99,6848.32 6969.99,7098.32 v1(7044.99,7098.32) 7145.02,6998.28 SW3.E
COL3: SW4.E U1.13 U9.1 U17.1 U25.1 | length 4228.2
  Top Layer w15: v1(5919.99,5448.32) 5969.99,5498.32 8094.99,5498.32 8134.98,5458.32 SW4.E
  Bottom Layer w15: U25.1 5905.23,5433.56 v1(5919.99,5448.32) ; 5905.23,5448.32 U17.1 U9.1 ; SW4.E 8184.99,5493.76 U1.13
ENC1_A: C2.2 R2.2 SW3.A U1.3 | length 1876.5
  Top Layer w15: v1(7469.99,6873.32) 7474.99,6878.32 U1.3
  Bottom Layer w15: R2.2 6901.77,6238.32 C2.2 6945.02,6301.81 SW3.A 7012.99,6423.32 7344.99,6423.32 7380.59,6458.92 7380.59,6783.92 v1(7469.99,6873.32)
ENC1_B: C1.2 R1.2 SW3.B U1.2 | length 1752.3
  Top Layer w15: v1(7619.99,6973.32) 8179.99,6973.32 U1.2
  Bottom Layer w15: R1.2 7202.03,6238.32 7218.45,6238.32 7145.02,6311.74 SW3.B 7377.02,6355.35 7405.59,6383.92 7405.59,6758.92 v1(7619.99,6973.32)
ENC1_SW: D15.2 SW3.D | length 461.6
  Bottom Layer w15: SW3.D 7022.93,6848.32 7269.99,6848.32 7328.83,6907.16 D15.2
ENC2_A: C4.2 R4.2 SW4.A U1.14 | length 2038.2
  Top Layer w15: v1(8344.99,5873.32) 8779.99,5873.32 U1.14
  Bottom Layer w15: R4.2 7924.49,4685.36 C4.2 7934.98,4821.77 SW4.A 8010.42,4948.32 8319.99,4948.32 8344.99,4973.32 v1(8344.99,5873.32)
ENC2_B: C3.2 R3.2 SW4.B U1.15 | length 1967.5
  Top Layer w15: v1(8419.99,5973.32) 8779.99,5973.32 U1.15
  Bottom Layer w15: R3.2 8207.95,4748.32 8208.45,4748.32 8134.98,4821.78 SW4.B 8369.55,4872.88 8419.99,4923.32 v1(8419.99,5973.32)
ENC2_SW: D16.2 SW4.D | length 186.1
  Bottom Layer w15: D16.2 7756.58,5443.75 SW4.D
GND: C1.1 C2.1 C3.1 C4.1 SW1.3 SW1.4 SW3.6 SW3.7 SW3.C SW4.6 SW4.7 SW4.C U1.4 U1.5 U1.24
  other v1: 8244.99,4318.32 5444.99,4858.32 6844.99,5138.32 5444.99,5807.32 3944.99,6252.88 7324.99,6388.32 6194.99,6411.54 4694.99,6422.48 7045.76,6641.52 7894.99,6728.32
ROW0: D1.1 D2.1 D3.1 D4.1 U1.6 | length 4410.2
  Top Layer w15: v1(4254.99,6373.32) 4404.99,6523.32 v1(5004.99,6523.32) 5154.99,6673.32 5729.99,6673.32 v1(5754.99,6698.32) 5929.99,6523.32 v1(6504.99,6523.32) 7469.99,6523.32 7519.99,6573.32 8179.99,6573.32 U1.6
  Bottom Layer w15: v1(4254.99,6373.32) D1.1 ; v1(5004.99,6523.32) D2.1 ; v1(5754.99,6698.32) D3.1 ; v1(6504.99,6523.32) D4.1
ROW1: D5.1 D6.1 D7.1 D8.1 U1.7 | length 5089.5
  Top Layer w15: v1(4254.99,5623.32) 4404.99,5773.32 v1(5004.99,5773.32) 5154.99,5923.32 5729.99,5923.32 v1(5754.99,5948.32) 5929.99,5773.32 v1(6504.99,5773.32) v1(7894.99,5773.32) ; v1(7894.99,6473.32) 7899.99,6478.32 U1.7
  Bottom Layer w15: v1(4254.99,5623.32) D5.1 ; v1(5004.99,5773.32) D6.1 ; v1(5754.99,5948.32) D7.1 ; v1(6504.99,5773.32) D8.1 ; v1(7894.99,5773.32) v1(7894.99,6473.32)
ROW2: D9.1 D10.1 D11.1 D12.1 U1.8 | length 5695.6
  Top Layer w15: v1(4254.99,4873.32) 4404.99,5023.32 v1(5004.99,5023.32) 5154.99,5173.32 5729.99,5173.32 v1(5754.99,5198.32) 5929.99,5023.32 v1(6504.99,5023.32) v1(7594.99,5023.32) ; v1(7594.99,6298.32) 7819.99,6298.32 7899.99,6378.32 U1.8
  Bottom Layer w15: v1(4254.99,4873.32) D9.1 ; v1(5004.99,5023.32) D10.1 ; v1(5754.99,5198.32) D11.1 ; v1(6504.99,5023.32) D12.1 ; v1(7594.99,5023.32) v1(7594.99,6298.32)
ROW3: D13.1 D14.1 D15.1 D16.1 U1.9 | length 4871.6
  Top Layer w15: v1(6644.99,4588.32) 7519.36,4588.32 7534.36,4573.32 v1(7544.99,4573.32) ; v1(7469.99,6923.32) v1(7644.99,6923.32) ; v1(7669.99,6223.32) 7694.99,6248.32 7844.99,6248.32 7874.99,6278.32 U1.9
  Bottom Layer w15: D13.1 v1(6644.99,4588.32) ; D14.1 7544.99,4172.16 v1(7544.99,4573.32) 7658.83,4687.16 D16.1 7658.83,6212.16 ; D15.1 7464.99,6928.32 v1(7469.99,6923.32) ; v1(7644.99,6923.32) 7544.99,6823.32 7544.99,6423.32 7658.83,6309.48 7658.83,6212.16 ; v1(7669.99,6223.32) 7658.83,6212.16
pads on no net: M1.1 M2.1 M3.1 M4.1 M5.1 M6.1 M7.1 SW1.5 SW2.3 SW2.6 U1.16 U1.17 U1.18 U1.19 U1.20 U1.21 U1.25

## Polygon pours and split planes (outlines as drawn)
GND on Top Layer (solid, remove dead copper, pour order 0): 3240.69,7248.58 9577.64,7248.58 9599.88,7226.35 9599.88,4002.29 8910.84,3264.52 3292.65,3272.86 3240.69,3439
GND on Bottom Layer (solid, remove dead copper, pour order 2): 3000,7420.86 9750.52,7420.86 9796.38,7466.72 9796.38,3256.81 9539.57,3000 3100.89,3000 3055.03,3045.86 3055.03,7365.83

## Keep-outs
Board Outline Layer:
  lines w10: 3445.06,6879.78 3445.32,4646.58 3540.32,4551.3 4245.05,4554.77 4295.05,4604.77 5006.94,4604.77 5806.94,3804.77 6402.82,3804.77 6802.82,3404.77 7095.05,3404.77 7705.46,4015.18 8556.35,4015.18 9218.1,4676.93 9218.1,7155.4 5095.05,7154.77 4945.05,7104.77 4345.05,7104.77 4195.05,6954.77 3519.08,6953.8 3445.06,6879.78

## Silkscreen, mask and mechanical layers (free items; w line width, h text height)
Top Silkscreen Layer:
  circle w10: c8035.72,5159.05 r1085.04
  text "KivoPad" at 7894.99,4608.32 h200
  text "by ARTITULE" at 7894.99,4508.32 h100
Bottom Silkscreen Layer:
  text "https://github.com/ARTITULE/KivoPad" at 8114.99,7028.32 h100
  text "RESET" at 9019.99,6923.32 h80 r90
  text "POWER" at 9119.99,6148.32 h80
  text "BAT+  BAT-" at 9169.99,5448.32 h80
  text "v1.0" at 8544.99,4028.32 h100
  text "Made on Earth by Humans" at 5834.99,3808.32 h85 r315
